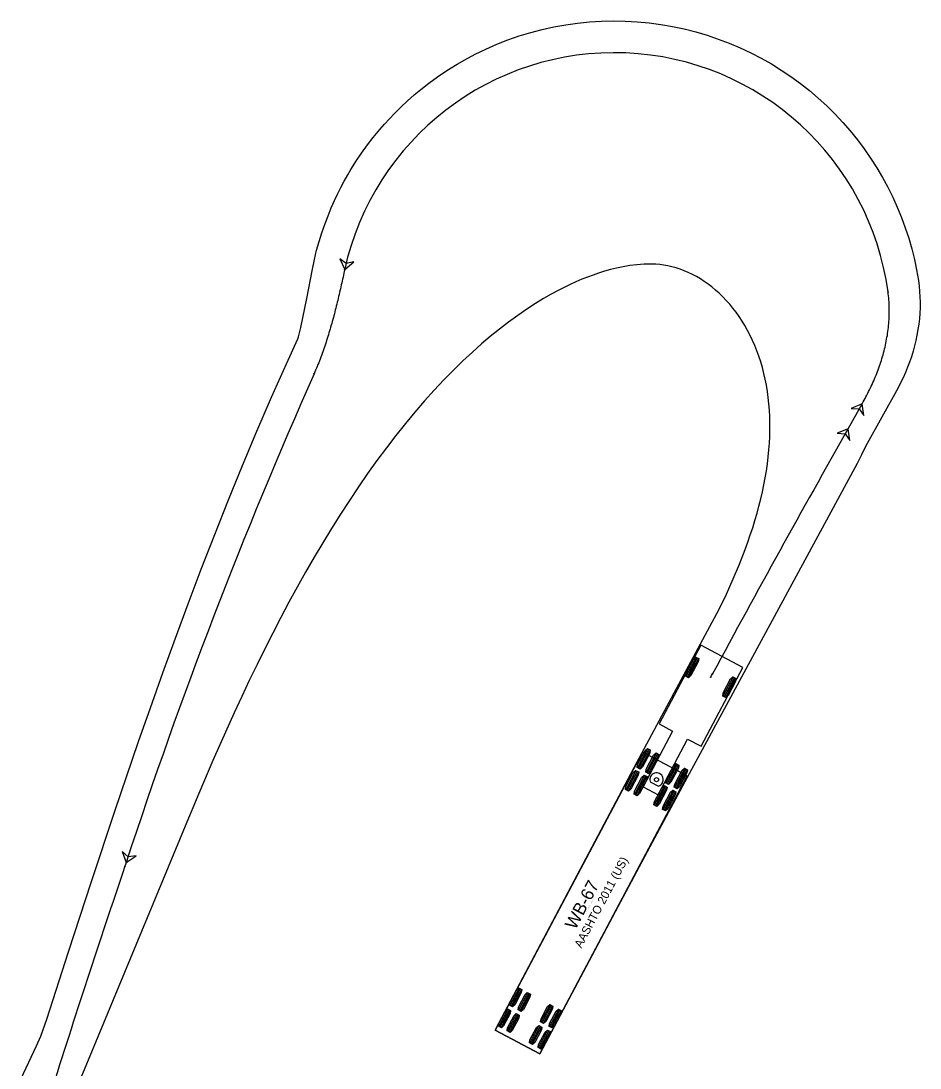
# Model space of a CAD drawing. Extents: x 2175591 to 2194071, y 76570 to 86955.
# Drawn here: x 2177029.2 to 2177180.7, y 78138.2 to 78314.5 of the extents above; entities that cross this region are included whole.
import ezdxf

# ---------------------------------------------------------------- set-up
doc = ezdxf.new("R2010")
doc.units = 0
doc.layers.add('C-UTIL-STRM-TEXT', color=7, linetype='Continuous')

msp = doc.modelspace()

# ---------------------------------------------------------------- linework, layer by layer
at = {"layer": 'C-UTIL-STRM-TEXT'}
for p, q in [((2177168.53, 78245.85), (2177170.9, 78250.05)), ((2177143.74, 78209.41), (2177136.71, 78196.15)), ((2177150.81, 78205.66), (2177143.74, 78209.41)), ((2177143.74, 78209.41), (2177143.74, 78209.41)), ((2177142.93, 78207.38), (2177141.21, 78204.14)), ((2177143.13, 78207.28), (2177141.41, 78204.04)), ((2177143.33, 78207.17), (2177141.62, 78203.93)), ((2177143.78, 78192.41), (2177150.81, 78205.66)), ((2177149.19, 78204.07), (2177147.47, 78200.83)), ((2177149.39, 78203.96), (2177147.67, 78200.72)), ((2177149.59, 78203.85), (2177147.87, 78200.61)), ((2177136.71, 78196.15), (2177138.98, 78194.95)), ((2177138.98, 78194.95), (2177134.02, 78185.58)), ((2177136.55, 78184.24), (2177141.52, 78193.61)), ((2177141.52, 78193.61), (2177143.78, 78192.41)), ((2177134.78, 78192.01), (2177133.06, 78188.77)), ((2177134.98, 78191.9), (2177133.26, 78188.66)), ((2177135.18, 78191.8), (2177133.47, 78188.56)), ((2177133.92, 78191.41), (2177109.1, 78144.58)), ((2177141.43, 78187.43), (2177133.92, 78191.41)), ((2177133.92, 78191.41), (2177133.92, 78191.41)), ((2177136.24, 78191.24), (2177134.52, 78188)), ((2177136.44, 78191.13), (2177134.72, 78187.89)), ((2177136.64, 78191.02), (2177134.92, 78187.78)), ((2177132.81, 78188.3), (2177131.09, 78185.06)), ((2177139.58, 78189.47), (2177137.86, 78186.23)), ((2177139.78, 78189.36), (2177138.06, 78186.12)), ((2177139.98, 78189.25), (2177138.27, 78186.01)), ((2177141.04, 78188.69), (2177139.32, 78185.45)), ((2177141.24, 78188.59), (2177139.52, 78185.35)), ((2177141.44, 78188.48), (2177139.72, 78185.24)), ((2177116.61, 78140.6), (2177141.43, 78187.43)), ((2177133.01, 78188.19), (2177131.3, 78184.95)), ((2177133.22, 78188.08), (2177131.5, 78184.84)), ((2177134.27, 78187.53), (2177132.55, 78184.29)), ((2177134.47, 78187.42), (2177132.75, 78184.18)), ((2177134.67, 78187.31), (2177132.96, 78184.07)), ((2177134.02, 78185.58), (2177136.55, 78184.24)), ((2177135.18, 78186.43), (2177136.6, 78185.68)), ((2177137.61, 78185.75), (2177135.89, 78182.51)), ((2177137.81, 78185.65), (2177136.1, 78182.41)), ((2177138.02, 78185.54), (2177136.3, 78182.3)), ((2177139.07, 78184.98), (2177137.35, 78181.74)), ((2177139.27, 78184.87), (2177137.55, 78181.63)), ((2177139.47, 78184.77), (2177137.76, 78181.53)), ((2177113.12, 78151.68), (2177111.57, 78148.76)), ((2177113.32, 78151.57), (2177111.77, 78148.65)), ((2177113.52, 78151.46), (2177111.97, 78148.54)), ((2177114.57, 78150.9), (2177113.03, 78147.99)), ((2177114.78, 78150.8), (2177113.23, 78147.88)), ((2177114.98, 78150.69), (2177113.43, 78147.77)), ((2177111.24, 78148.14), (2177109.7, 78145.23)), ((2177111.44, 78148.03), (2177109.9, 78145.12)), ((2177111.65, 78147.93), (2177110.1, 78145.01)), ((2177118.36, 78148.9), (2177116.81, 78145.98)), ((2177118.56, 78148.79), (2177117.01, 78145.87)), ((2177118.76, 78148.68), (2177117.22, 78145.77)), ((2177119.82, 78148.12), (2177118.27, 78145.21)), ((2177120.02, 78148.02), (2177118.47, 78145.1)), ((2177120.22, 78147.91), (2177118.67, 78144.99)), ((2177112.7, 78147.37), (2177111.15, 78144.45)), ((2177112.9, 78147.26), (2177111.36, 78144.35)), ((2177113.1, 78147.15), (2177111.56, 78144.24)), ((2177109.1, 78144.58), (2177116.61, 78140.6)), ((2177116.48, 78145.36), (2177114.94, 78142.45)), ((2177116.69, 78145.25), (2177115.14, 78142.34)), ((2177116.89, 78145.15), (2177115.34, 78142.23)), ((2177117.94, 78144.59), (2177116.4, 78141.67)), ((2177118.14, 78144.48), (2177116.6, 78141.57)), ((2177118.35, 78144.37), (2177116.8, 78141.46))]:
    msp.add_line(p, q, dxfattribs=at)
for points in [[(2177029.24, 78136.37), (2177031.84, 78141.94), (2177032.6, 78143.6), (2177033.58, 78146.47), (2177037.25, 78157.79), (2177041.12, 78169.62), (2177045.07, 78181.47), (2177049.06, 78193.2), (2177051.04, 78198.87), (2177053.13, 78204.74), (2177055.25, 78210.57), (2177057.41, 78216.38), (2177059.61, 78222.19), (2177061.88, 78228.03), (2177064.19, 78233.85), (2177066.56, 78239.65), (2177068.97, 78245.41), (2177071.43, 78251.13), (2177073.94, 78256.77), (2177075.85, 78260.95), (2177075.99, 78261.31), (2177076.37, 78262.9), (2177076.73, 78264.51), (2177077.4, 78267.78), (2177078.32, 78272.72), (2177078.66, 78274.32), (2177079.04, 78275.87), (2177079.46, 78277.36), (2177079.91, 78278.8), (2177080.45, 78280.36), (2177080.96, 78281.7), (2177081.5, 78283), (2177082.05, 78284.25), (2177082.62, 78285.44), (2177083.11, 78286.43), (2177083.7, 78287.53), (2177084.27, 78288.55), (2177084.82, 78289.48), (2177085.76, 78290.97), (2177086.62, 78292.25), (2177087.59, 78293.6), (2177088.56, 78294.86), (2177089.67, 78296.21), (2177090.46, 78297.12), (2177091.29, 78298.03), (2177092.14, 78298.92), (2177093.22, 78299.99), (2177094.34, 78301.03), (2177095.46, 78302.02), (2177096.57, 78302.94), (2177097.93, 78304.01), (2177099.41, 78305.08), (2177100.99, 78306.15), (2177102.68, 78307.2), (2177103.97, 78307.94), (2177105.74, 78308.88), (2177107.55, 78309.75), (2177109.39, 78310.56), (2177111.26, 78311.29), (2177113.17, 78311.95), (2177115.09, 78312.53), (2177117.04, 78313.04), (2177119.01, 78313.47), (2177120.99, 78313.83), (2177122.98, 78314.11), (2177124.98, 78314.31), (2177126.99, 78314.44), (2177129, 78314.48), (2177131.01, 78314.45), (2177133.02, 78314.34), (2177135.02, 78314.15), (2177137.01, 78313.89), (2177138.98, 78313.55), (2177140.94, 78313.13), (2177142.87, 78312.64), (2177144.79, 78312.08), (2177146.67, 78311.44), (2177148.53, 78310.74), (2177150.36, 78309.96), (2177152.15, 78309.12), (2177153.9, 78308.21), (2177155.62, 78307.24), (2177157.29, 78306.2), (2177158.92, 78305.11), (2177160.5, 78303.96), (2177162.03, 78302.75), (2177163.52, 78301.49), (2177164.95, 78300.18), (2177166.32, 78298.82), (2177167.64, 78297.41), (2177168.9, 78295.96), (2177170.11, 78294.47), (2177171.25, 78292.94), (2177172.34, 78291.38), (2177173.36, 78289.78), (2177174.32, 78288.15), (2177175.22, 78286.5), (2177176.05, 78284.82), (2177176.82, 78283.11), (2177177.52, 78281.39), (2177178.16, 78279.65), (2177178.74, 78277.89), (2177179.25, 78276.13), (2177179.7, 78274.35), (2177180.08, 78272.56), (2177180.24, 78271.67), (2177180.39, 78270.77), (2177180.5, 78269.86), (2177180.59, 78268.95), (2177180.64, 78268.04), (2177180.66, 78267.12), (2177180.65, 78266.2), (2177180.61, 78265.28), (2177180.54, 78264.36), (2177180.43, 78263.44), (2177180.3, 78262.52), (2177180.14, 78261.6), (2177179.94, 78260.69), (2177179.72, 78259.77), (2177179.47, 78258.87), (2177179.19, 78257.96), (2177178.89, 78257.07), (2177178.55, 78256.18), (2177178.19, 78255.29), (2177177.8, 78254.42), (2177177.39, 78253.55), (2177176.95, 78252.7), (2177171.49, 78242.87), (2177170.78, 78241.42), (2177170.05, 78239.99), (2177141.02, 78186.4), (2177135.15, 78175.47), (2177129.29, 78164.5), (2177116.61, 78140.6), (2177109.1, 78144.58), (2177109.23, 78144.83), (2177109.23, 78144.83)], [(2177109.23, 78144.83), (2177132.54, 78188.81), (2177138, 78199.08), (2177143.67, 78209.62), (2177146.82, 78215.44), (2177148.05, 78218.01), (2177149.19, 78220.55), (2177150.24, 78223.05), (2177151.2, 78225.51), (2177151.65, 78226.73), (2177152.07, 78227.96), (2177152.47, 78229.18), (2177152.85, 78230.4), (2177153.21, 78231.61), (2177153.53, 78232.82), (2177153.84, 78234.02), (2177154.11, 78235.22), (2177154.36, 78236.41), (2177154.59, 78237.6), (2177154.78, 78238.77), (2177154.95, 78239.94), (2177155.09, 78241.1), (2177155.2, 78242.26), (2177155.29, 78243.4), (2177155.34, 78244.53), (2177155.37, 78245.66), (2177155.37, 78246.77), (2177155.34, 78247.87), (2177155.28, 78248.95), (2177155.2, 78250.02), (2177155.08, 78251.08), (2177154.94, 78252.13), (2177154.77, 78253.15), (2177154.57, 78254.17), (2177154.35, 78255.16), (2177154.1, 78256.13), (2177153.82, 78257.09), (2177153.51, 78258.03), (2177153.18, 78258.94), (2177152.83, 78259.84), (2177152.45, 78260.71), (2177152.04, 78261.56), (2177151.61, 78262.39), (2177151.16, 78263.19), (2177150.69, 78263.97), (2177150.2, 78264.72), (2177149.69, 78265.44), (2177149.15, 78266.14), (2177148.6, 78266.81), (2177148.03, 78267.45), (2177147.45, 78268.06), (2177146.85, 78268.64), (2177146.23, 78269.19), (2177145.61, 78269.7), (2177144.97, 78270.19), (2177144.32, 78270.65), (2177143.66, 78271.07), (2177142.99, 78271.46), (2177142.31, 78271.81), (2177141.63, 78272.14), (2177140.95, 78272.43), (2177140.26, 78272.68), (2177139.57, 78272.9), (2177138.88, 78273.09), (2177138.2, 78273.25), (2177137.51, 78273.37), (2177136.84, 78273.46), (2177136.17, 78273.52), (2177135.5, 78273.55), (2177134.85, 78273.56), (2177134.21, 78273.54), (2177132.97, 78273.45), (2177131.78, 78273.31), (2177130.65, 78273.11), (2177129.56, 78272.88), (2177128.52, 78272.63), (2177127.51, 78272.34), (2177126.53, 78272.03), (2177125.58, 78271.71), (2177124.64, 78271.36), (2177123.72, 78270.99), (2177122.71, 78270.56), (2177121.75, 78270.12), (2177120.72, 78269.62), (2177119.71, 78269.11), (2177118.54, 78268.47), (2177117.26, 78267.74), (2177115.88, 78266.9), (2177114.42, 78265.95), (2177112.92, 78264.92), (2177111.37, 78263.79), (2177109.81, 78262.59), (2177108.26, 78261.35), (2177106.83, 78260.13), (2177105.26, 78258.73), (2177103.67, 78257.25), (2177102.08, 78255.7), (2177100.46, 78254.05), (2177098.84, 78252.33), (2177097.22, 78250.53), (2177095.6, 78248.65), (2177093.99, 78246.71), (2177092.38, 78244.7), (2177090.78, 78242.63), (2177089.2, 78240.5), (2177087.63, 78238.31), (2177086.08, 78236.07), (2177084.55, 78233.78), (2177083.03, 78231.45), (2177081.54, 78229.07), (2177080.07, 78226.65), (2177078.61, 78224.2), (2177077.18, 78221.71), (2177075.77, 78219.18), (2177074.38, 78216.63), (2177073.01, 78214.05), (2177071.65, 78211.44), (2177070.32, 78208.8), (2177069, 78206.13), (2177067.7, 78203.45), (2177066.42, 78200.74), (2177065.15, 78198.02), (2177063.91, 78195.29), (2177061.56, 78189.99), (2177059.18, 78184.44), (2177056.88, 78178.95), (2177039.35, 78136.55)], [(2177083.77, 78272.65), (2177083.7, 78272.32), (2177083.63, 78272), (2177083.55, 78271.67), (2177083.48, 78271.35), (2177083.41, 78271.02), (2177083.34, 78270.7), (2177083.26, 78270.37), (2177083.19, 78270.05), (2177083.12, 78269.72), (2177083.04, 78269.4), (2177082.97, 78269.07), (2177082.89, 78268.75), (2177082.81, 78268.42), (2177082.74, 78268.1), (2177082.66, 78267.78), (2177082.58, 78267.45), (2177082.5, 78267.13), (2177082.43, 78266.8), (2177082.35, 78266.48), (2177082.26, 78266.16), (2177082.18, 78265.83), (2177082.1, 78265.51), (2177082.02, 78265.19), (2177081.93, 78264.87), (2177081.85, 78264.54), (2177081.76, 78264.22), (2177081.67, 78263.9), (2177081.58, 78263.58), (2177081.49, 78263.26), (2177081.4, 78262.94), (2177081.31, 78262.62), (2177081.21, 78262.3), (2177081.12, 78261.98), (2177081.02, 78261.66), (2177080.92, 78261.34), (2177080.82, 78261.02), (2177080.72, 78260.7), (2177080.62, 78260.39), (2177080.52, 78260.07), (2177080.41, 78259.75), (2177080.3, 78259.44), (2177080.2, 78259.12), (2177080.08, 78258.81), (2177079.97, 78258.5), (2177079.86, 78258.18), (2177079.74, 78257.87), (2177079.62, 78257.56), (2177079.5, 78257.25), (2177079.38, 78256.94), (2177079.26, 78256.63), (2177079.13, 78256.32), (2177079, 78256.01), (2177078.87, 78255.7), (2177078.74, 78255.4), (2177078.61, 78255.09)], [(2177170.9, 78250.05), (2177171.07, 78250.34), (2177171.23, 78250.63), (2177171.39, 78250.92), (2177171.55, 78251.21), (2177171.7, 78251.51), (2177171.85, 78251.81), (2177172, 78252.1), (2177172.15, 78252.4), (2177172.3, 78252.7), (2177172.44, 78253), (2177172.58, 78253.31), (2177172.72, 78253.61), (2177172.85, 78253.91), (2177172.98, 78254.22), (2177173.11, 78254.53), (2177173.24, 78254.84), (2177173.36, 78255.15), (2177173.48, 78255.46), (2177173.6, 78255.77), (2177173.72, 78256.08), (2177173.83, 78256.4), (2177173.94, 78256.71), (2177174.04, 78257.03), (2177174.14, 78257.34), (2177174.24, 78257.66), (2177174.34, 78257.98), (2177174.43, 78258.3), (2177174.52, 78258.62), (2177174.6, 78258.95), (2177174.68, 78259.27), (2177174.76, 78259.59), (2177174.83, 78259.92), (2177174.9, 78260.25), (2177174.97, 78260.57), (2177175.03, 78260.9), (2177175.09, 78261.23), (2177175.15, 78261.56), (2177175.2, 78261.89), (2177175.24, 78262.22), (2177175.29, 78262.55), (2177175.33, 78262.88), (2177175.36, 78263.21), (2177175.39, 78263.54), (2177175.42, 78263.87), (2177175.44, 78264.21), (2177175.46, 78264.54), (2177175.47, 78264.87), (2177175.48, 78265.21), (2177175.48, 78265.54), (2177175.48, 78265.87), (2177175.48, 78266.21), (2177175.47, 78266.54), (2177175.45, 78266.87), (2177175.43, 78267.2), (2177175.41, 78267.54), (2177175.38, 78267.87), (2177175.35, 78268.2), (2177175.31, 78268.53), (2177175.27, 78268.86)], [(2177145.4, 78204), (2177145.56, 78204.29), (2177145.71, 78204.59)], [(2177046.97, 78172.82), (2177046.86, 78172.5), (2177046.76, 78172.18)]]:
    msp.add_lwpolyline(points, dxfattribs=at)
for points in [[(2177083.77, 78272.65), (2177085.3, 78273.94), (2177083.99, 78273.63), (2177082.92, 78274.46)], [(2177170.9, 78250.05), (2177169.06, 78249.26), (2177170.41, 78249.18), (2177171.18, 78248.07)], [(2177168.53, 78245.85), (2177166.69, 78245.07), (2177168.04, 78244.98), (2177168.81, 78243.87)], [(2177142.88, 78207.41), (2177143.38, 78207.14), (2177143.29, 78206.61), (2177142.06, 78204.28), (2177141.67, 78203.9), (2177141.16, 78204.17), (2177141.25, 78204.7), (2177142.48, 78207.04)], [(2177149.14, 78204.09), (2177149.64, 78203.82), (2177149.55, 78203.29), (2177148.32, 78200.96), (2177147.92, 78200.59), (2177147.42, 78200.85), (2177147.51, 78201.39), (2177148.74, 78203.72)], [(2177134.73, 78192.04), (2177135.23, 78191.77), (2177135.15, 78191.23), (2177133.91, 78188.9), (2177133.52, 78188.53), (2177133.01, 78188.8), (2177133.1, 78189.33), (2177134.34, 78191.66)], [(2177136.19, 78191.26), (2177136.69, 78191), (2177136.6, 78190.46), (2177135.37, 78188.13), (2177134.97, 78187.76), (2177134.47, 78188.02), (2177134.56, 78188.56), (2177135.79, 78190.89)], [(2177132.76, 78188.33), (2177133.27, 78188.06), (2177133.18, 78187.52), (2177131.94, 78185.19), (2177131.55, 78184.82), (2177131.04, 78185.09), (2177131.13, 78185.62), (2177132.37, 78187.95)], [(2177139.53, 78189.49), (2177140.03, 78189.22), (2177139.95, 78188.69), (2177138.71, 78186.36), (2177138.32, 78185.98), (2177137.81, 78186.25), (2177137.9, 78186.79), (2177139.14, 78189.12)], [(2177140.99, 78188.72), (2177141.49, 78188.45), (2177141.4, 78187.92), (2177140.17, 78185.58), (2177139.77, 78185.21), (2177139.27, 78185.48), (2177139.36, 78186.01), (2177140.59, 78188.35)], [(2177134.22, 78187.55), (2177134.72, 78187.29), (2177134.64, 78186.75), (2177133.4, 78184.42), (2177133.01, 78184.05), (2177132.5, 78184.31), (2177132.59, 78184.85), (2177133.83, 78187.18)], [(2177137.56, 78185.78), (2177138.07, 78185.51), (2177137.98, 78184.98), (2177136.74, 78182.65), (2177136.35, 78182.27), (2177135.84, 78182.54), (2177135.93, 78183.08), (2177137.17, 78185.41)], [(2177139.02, 78185.01), (2177139.52, 78184.74), (2177139.44, 78184.21), (2177138.2, 78181.87), (2177137.81, 78181.5), (2177137.3, 78181.77), (2177137.39, 78182.3), (2177138.63, 78184.64)], [(2177046.97, 78172.82), (2177048.62, 78173.95), (2177047.28, 78173.77), (2177046.3, 78174.7)], [(2177113.06, 78151.7), (2177113.57, 78151.43), (2177113.51, 78150.95), (2177112.39, 78148.85), (2177112.02, 78148.52), (2177111.52, 78148.79), (2177111.58, 78149.28), (2177112.7, 78151.37)], [(2177114.52, 78150.93), (2177115.03, 78150.66), (2177114.96, 78150.17), (2177113.85, 78148.07), (2177113.48, 78147.75), (2177112.98, 78148.01), (2177113.04, 78148.5), (2177114.15, 78150.6)], [(2177111.19, 78148.17), (2177111.7, 78147.9), (2177111.63, 78147.41), (2177110.52, 78145.31), (2177110.15, 78144.98), (2177109.65, 78145.25), (2177109.71, 78145.74), (2177110.82, 78147.84)], [(2177118.31, 78148.92), (2177118.81, 78148.66), (2177118.75, 78148.17), (2177117.64, 78146.07), (2177117.27, 78145.74), (2177116.76, 78146.01), (2177116.83, 78146.5), (2177117.94, 78148.6)], [(2177119.77, 78148.15), (2177120.27, 78147.88), (2177120.21, 78147.39), (2177119.09, 78145.29), (2177118.73, 78144.97), (2177118.22, 78145.23), (2177118.28, 78145.72), (2177119.4, 78147.82)], [(2177112.65, 78147.39), (2177113.15, 78147.13), (2177113.09, 78146.64), (2177111.98, 78144.54), (2177111.61, 78144.21), (2177111.1, 78144.48), (2177111.17, 78144.97), (2177112.28, 78147.07)], [(2177116.43, 78145.39), (2177116.94, 78145.12), (2177116.88, 78144.63), (2177115.76, 78142.53), (2177115.39, 78142.21), (2177114.89, 78142.47), (2177114.95, 78142.96), (2177116.07, 78145.06)], [(2177117.89, 78144.62), (2177118.4, 78144.35), (2177118.33, 78143.86), (2177117.22, 78141.76), (2177116.85, 78141.43), (2177116.35, 78141.7), (2177116.41, 78142.19), (2177117.52, 78144.29)]]:
    msp.add_lwpolyline(points, close=True, dxfattribs=at)
for centre, radius in [((2177083.77, 78272.65), 0.0417), ((2177083.77, 78272.65), 0.0417), ((2177175.27, 78268.86), 0.0417), ((2177175.27, 78268.86), 0.0417), ((2177078.61, 78255.09), 0.0417), ((2177078.61, 78255.09), 0.0417), ((2177170.9, 78250.05), 0.0417), ((2177170.9, 78250.05), 0.0417), ((2177168.53, 78245.85), 0.0417), ((2177168.53, 78245.85), 0.0417), ((2177145.71, 78204.59), 0.0417), ((2177145.71, 78204.59), 0.0417), ((2177145.4, 78204), 0.0417), ((2177136.27, 78186.77), 0.34), ((2177046.97, 78172.82), 0.0417), ((2177046.97, 78172.82), 0.0417), ((2177046.76, 78172.18), 0.0417), ((2177046.76, 78172.18), 0.0417)]:
    msp.add_circle(centre, radius, dxfattribs=at)
for centre, radius, start, end in [((2177129.18, 78262.62), 46.51, 7.7094, 167.5493), ((2177867.3, 77904.56), 863.08, 156.03727, 161.89162), ((2179307.59, 77036.22), 2457.39, 150.5118, 151.61132), ((2177136.27, 78186.77), 1.14, 287.0733, 197.0733), ((2178767.68, 77587.58), 1817.51, 161.23707, 162.50486)]:
    msp.add_arc(centre, radius, start, end, dxfattribs=at)

# ---------------------------------------------------------------- texts
for s, height, p in [('AASHTO 2011 (US)', 1.4167, (2177123.6, 78158.32)), ('WB-67', 2.125, (2177122.62, 78161.39)), ('(c) 2019 Transoft Solutions, Inc. All rights reserved.', 0.085, (2177124.49, 78164.45))]:
    msp.add_text(s, height=height, rotation=62.0733, dxfattribs=at).set_placement(p)

doc.saveas('drawing.dxf')
